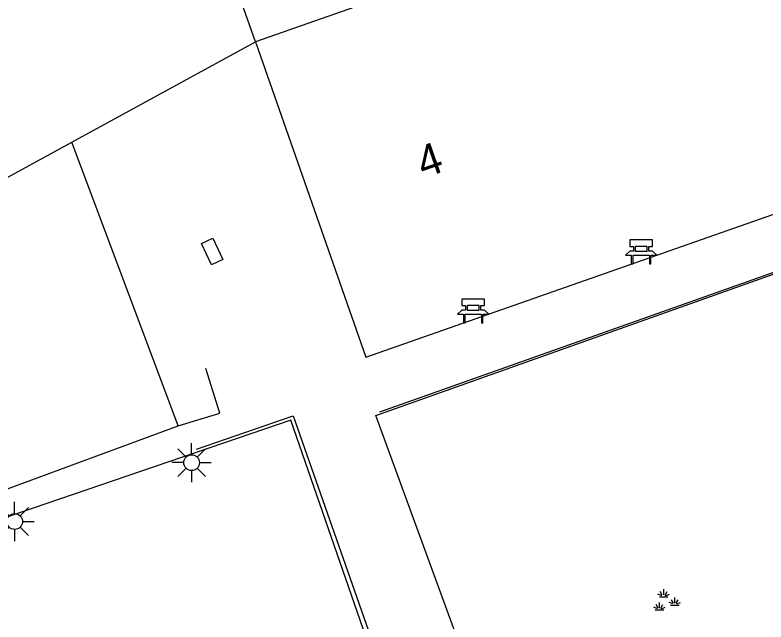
# Model space of a CAD drawing. Extents: x 135999 to 138000, y 396000 to 398501.
# Drawn here: x 136374.91 to 136398.82, y 396465.85 to 396485.17 of the extents above; entities that cross this region are included whole.
import ezdxf

# ---------------------------------------------------------------- set-up
doc = ezdxf.new("R2010")
doc.units = 0
for name, color, linetype in [('bs-afsc-hekwerk laag', 7, 'Continuous'), ('gg-afsc-erfafscheiding', 7, 'Continuous'), ('gg-afsc-hekwerk', 7, 'Continuous'), ('gg-anno-huisnummerreeks BGT', 7, 'Continuous'), ('gg-bbg-hoofdgebouw', 7, 'Continuous'), ('gg-knt-verharding', 7, 'Continuous'), ('gt-symb-bank', 7, 'Continuous'), ('gt-symb-groenvak', 7, 'Continuous'), ('gt-symb-kolk center center', 7, 'Continuous'), ('gt-symb-lichtmast', 7, 'Continuous')]:
    doc.layers.add(name, color=color, linetype=linetype)

# ---------------------------------------------------------------- blocks, each defined once
blk = doc.blocks.new('gt0-BANK')
at = {"layer": 'gt-symb-bank'}
for p, q in [((-0.243, 0.547), (-0.243, 0.412)), ((0.244, 0.487), (0.244, 0.547)), ((-0.504, 0.274), (-0.322, 0.274)), ((-0.314, 0.265), (-0.314, 0.007)), ((-0.258, 0.009), (-0.258, 0.265)), ((-0.251, 0.274), (0.252, 0.274)), ((0.26, 0.265), (0.26, 0.007)), ((0.311, 0.007), (0.311, 0.265)), ((0.319, 0.274), (0.501, 0.274)), ((-0.308, 0), (-0.266, 0)), ((0.266, 0), (0.305, 0))]:
    blk.add_line(p, q, dxfattribs=at)
for points in [[(-0.362, 0.761), (-0.362, 0.554), (-0.251, 0.554)], [(0.252, 0.554), (0.359, 0.554), (0.359, 0.761), (-0.362, 0.761)], [(-0.251, 0.404), (-0.362, 0.404), (-0.504, 0.274)], [(0.501, 0.274), (0.359, 0.404), (0.244, 0.404)]]:
    blk.add_lwpolyline(points, dxfattribs=at)
for centre, start, end in [((-0.308, 0.007), 180, 270), ((0.266, 0.007), 180, 270), ((0.305, 0.007), 270, 0)]:
    blk.add_arc(centre, 0.00643, start, end, dxfattribs=at)
for points, degree in [([(-0.251, 0.554), (-0.243, 0.553), (-0.243, 0.547)], 2), ([(-0.18, 0.554), (0, 0.554), (0.18, 0.554), (0.189, 0.553), (0.189, 0.547), (0.189, 0.48), (0.189, 0.412), (0.189, 0.404), (0.18, 0.404), (0, 0.404), (-0.18, 0.404), (-0.188, 0.404), (-0.188, 0.412), (-0.188, 0.48), (-0.188, 0.547), (-0.186, 0.554), (-0.18, 0.554)], 3), ([(0.244, 0.547), (0.245, 0.554), (0.252, 0.554)], 2), ([(0.244, 0.404), (0.244, 0.462), (0.244, 0.487)], 2), ([(-0.322, 0.274), (-0.314, 0.273), (-0.314, 0.265)], 2), ([(-0.258, 0.265), (-0.257, 0.274), (-0.251, 0.274)], 2), ([(-0.243, 0.412), (-0.243, 0.404), (-0.251, 0.404)], 2), ([(0.252, 0.274), (0.26, 0.273), (0.26, 0.265)], 2), ([(0.311, 0.265), (0.312, 0.274), (0.319, 0.274)], 2), ([(-0.266, 0), (-0.258, 0), (-0.258, 0.009)], 2)]:
    blk.add_open_spline(points, degree=degree, dxfattribs=at)
blk = doc.blocks.new('gt0-KOLKCC')
at = {"layer": 'gt-symb-kolk center center'}
blk.add_lwpolyline([(-0.375, 0.2), (0.375, 0.2), (0.375, -0.2), (-0.375, -0.2)], close=True, dxfattribs=at)
blk = doc.blocks.new('gt0-LMAST')
at = {"layer": 'gt-symb-lichtmast'}
for p, q in [((-0.005, 0.246), (-0.005, 0.621)), ((-0.182, 0.173), (-0.447, 0.438)), ((0.172, 0.173), (0.437, 0.438)), ((-0.255, -0.004), (-0.63, -0.004)), ((-0.182, -0.181), (-0.447, -0.446)), ((0.437, -0.446), (0.172, -0.181)), ((0.245, -0.004), (0.62, -0.004)), ((-0.005, -0.254), (-0.005, -0.629))]:
    blk.add_line(p, q, dxfattribs=at)
blk.add_circle((-0.005, -0.004), 0.25, dxfattribs=at)
blk = doc.blocks.new('gt0-GRVAK')
at = {"layer": 'gt-symb-groenvak'}
for p, q in [((-0.11, 0.189), (-0.228, 0.24)), ((-0.091, 0.211), (-0.156, 0.322)), ((-0.047, 0.214), (-0.047, 0.393)), ((-0.004, 0.211), (0.061, 0.322)), ((0.015, 0.189), (0.133, 0.24)), ((-0.182, 0.153), (0.088, 0.153)), ((0.262, -0.052), (0.197, 0.059)), ((0.305, -0.049), (0.305, 0.13)), ((0.349, -0.052), (0.414, 0.059)), ((-0.245, -0.228), (-0.363, -0.177)), ((-0.226, -0.206), (-0.291, -0.095)), ((-0.183, -0.203), (-0.183, -0.024)), ((-0.139, -0.206), (-0.074, -0.095)), ((-0.12, -0.228), (-0.002, -0.177)), ((0.243, -0.074), (0.125, -0.023)), ((0.17, -0.11), (0.441, -0.11)), ((0.368, -0.074), (0.486, -0.023)), ((-0.318, -0.264), (-0.047, -0.264))]:
    blk.add_line(p, q, dxfattribs=at)

msp = doc.modelspace()

# ---------------------------------------------------------------- linework, layer by layer
at = {"layer": 'bs-afsc-hekwerk laag'}
msp.add_line((136400.282, 396477.41), (136386.518, 396472.532), dxfattribs=at)
msp.add_lwpolyline([(136380.685, 396471.353), (136383.764, 396472.41), (136388.18, 396459.818), (136379.182, 396456.637)], dxfattribs=at)
at = {"layer": 'gg-afsc-erfafscheiding'}
msp.add_line((136370.404, 396468.519), (136380.106, 396472.089), dxfattribs=at)
msp.add_lwpolyline([(136380.106, 396472.089), (136381.434, 396472.495), (136380.986, 396473.921)], dxfattribs=at)
at = {"layer": 'gg-afsc-hekwerk'}
for p, q in [((136376.713, 396481.124), (136382.56, 396484.32)), ((136364.811, 396474.617), (136376.713, 396481.124)), ((136400.282, 396477.41), (136386.518, 396472.532))]:
    msp.add_line(p, q, dxfattribs=at)
msp.add_lwpolyline([(136380.685, 396471.353), (136383.764, 396472.41), (136388.18, 396459.818), (136379.182, 396456.637)], dxfattribs=at)
at = {"layer": 'gg-bbg-hoofdgebouw'}
msp.add_line((136382.56, 396484.32), (136386.08, 396474.28), dxfattribs=at)
msp.add_lwpolyline([(136386.08, 396474.28), (136410.361, 396482.793), (136406.841, 396492.833), (136382.56, 396484.32)], dxfattribs=at)
at = {"layer": 'gg-knt-verharding'}
msp.add_line((136380.106, 396472.089), (136376.713, 396481.124), dxfattribs=at)
for points in [[(136382.56, 396484.32), (136381.568, 396487.149), (136407.347, 396496.249)], [(136399.002, 396462.275), (136391.103, 396459.574), (136386.397, 396472.425), (136400.543, 396477.45), (136405.246, 396464.398), (136404.058, 396464.09)], [(136375.412, 396456.99), (136387.564, 396461.094), (136383.689, 396472.27), (136371.556, 396468.138), (136375.412, 396456.99)]]:
    msp.add_lwpolyline(points, dxfattribs=at)

# ---------------------------------------------------------------- block references
at = {"layer": 'gt-symb-bank'}
for p in [(136394.845, 396477.248), (136389.497, 396475.369)]:
    msp.add_blockref('gt0-BANK', p, dxfattribs=at)
at = {"layer": 'gt-symb-groenvak'}
msp.add_blockref('gt0-GRVAK', (136395.608, 396466.495), dxfattribs=at)
at = {"layer": 'gt-symb-kolk center center', "rotation": 115.20722121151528}
msp.add_blockref('gt0-KOLKCC', (136381.187, 396477.639), dxfattribs=at)
at = {"layer": 'gt-symb-lichtmast'}
for p in [(136380.536, 396470.924), (136374.902, 396469.05)]:
    msp.add_blockref('gt0-LMAST', p, dxfattribs=at)

# ---------------------------------------------------------------- texts
at = {"layer": 'gg-anno-huisnummerreeks BGT'}
msp.add_text('4', height=1, rotation=19.3, dxfattribs=at).set_placement((136387.912, 396479.968))

doc.saveas('drawing.dxf')
